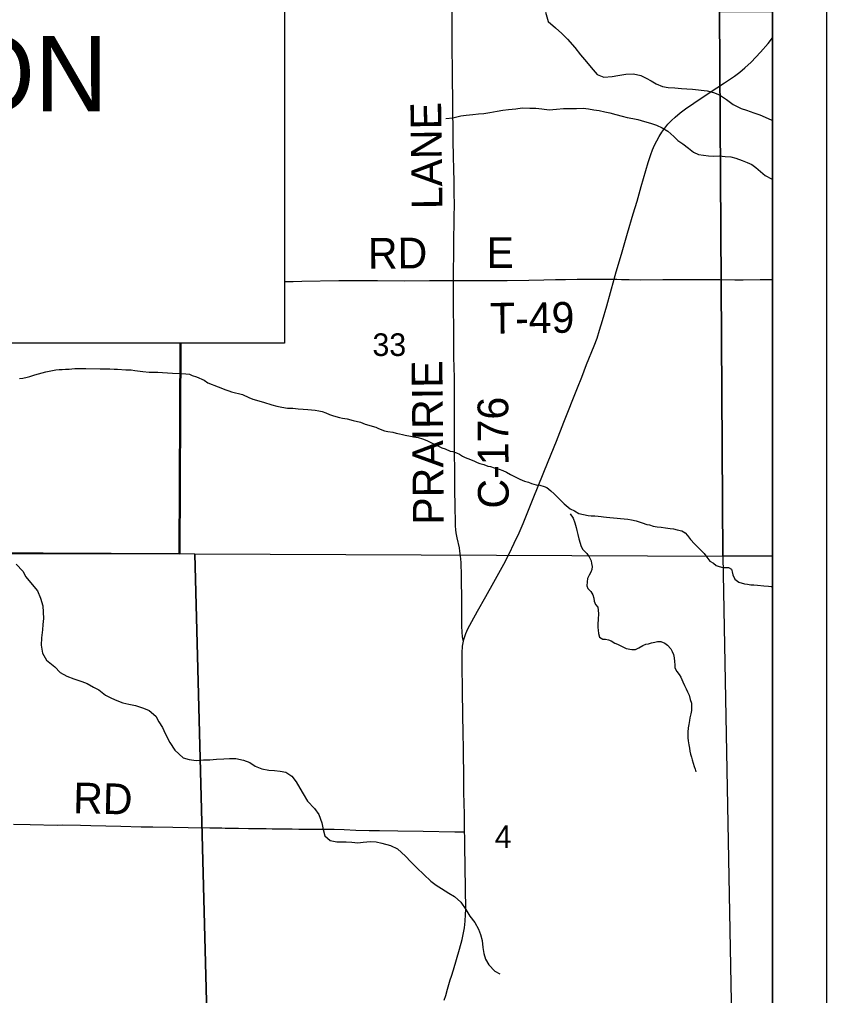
# Model space of a CAD drawing. Extents: x 0 to 34, y 0 to 22.
# Drawn here: x 7.507 to 9, y 15.055 to 16.861 of the extents above; entities that cross this region are included whole.
import ezdxf

# ---------------------------------------------------------------- set-up
doc = ezdxf.new("R2010")
doc.units = 0
for name, color, linetype in [('Default', 7, 'Continuous'), ('GM_X_County_Road', 7, 'Continuous'), ('GM_X_County_Road_Text', 7, 'Continuous'), ('GM_X_Minor_River', 7, 'Continuous'), ('GM_X_Section', 7, 'Continuous'), ('GM_X_Section_Text', 7, 'Continuous'), ('GM_X_State_Route', 7, 'Continuous'), ('GM_X_Township_Road', 7, 'Continuous'), ('GM_X_Township_Road_Text', 7, 'Continuous'), ('SH_Data', 7, 'Continuous'), ('SH_Text', 7, 'Continuous')]:
    doc.layers.add(name, color=color, linetype=linetype)

msp = doc.modelspace()

# ---------------------------------------------------------------- linework, layer by layer
at = {"layer": 'Default'}
for points in [[(8.9, 15.8688), (8.9, 16.8757), (8.802, 16.8756), (8.808, 15.8683)], [(8.9, 14.8441), (8.9, 15.8688), (8.808, 15.8683), (8.8276, 14.8459)]]:
    msp.add_lwpolyline(points, close=True, dxfattribs=at)
at = {"layer": 'GM_X_County_Road'}
for points in [[(8.3101, 16.3785), (8.3101, 16.3991), (8.3103, 16.4239), (8.3109, 16.458), (8.3112, 16.4828), (8.3115, 16.5014), (8.3117, 16.5138), (8.3116, 16.5231), (8.3115, 16.5355), (8.311, 16.5633), (8.3109, 16.5823), (8.3101, 16.61), (8.3096, 16.6348), (8.3093, 16.6501), (8.3091, 16.6686), (8.3089, 16.681), (8.3086, 16.7089), (8.3082, 16.7555), (8.3076, 16.8206), (8.3073, 16.8765)], [(8.3284, 15.7107), (8.3274, 15.7154), (8.3266, 15.7195), (8.326, 15.7272), (8.3257, 15.7394), (8.3251, 15.7821), (8.3245, 15.8316), (8.3239, 15.8564), (8.3231, 15.8686), (8.3219, 15.8777), (8.3209, 15.8838), (8.317, 15.9019), (8.3164, 15.9052), (8.3157, 15.9086), (8.3152, 15.9116), (8.3145, 15.9172), (8.3139, 15.9246), (8.3136, 15.9374), (8.3132, 15.9533), (8.3128, 15.9696), (8.3127, 15.9826), (8.3125, 15.9984), (8.3126, 16.0197), (8.3121, 16.0656), (8.3119, 16.0966), (8.3118, 16.1184), (8.3118, 16.1494), (8.3118, 16.168), (8.3116, 16.1928), (8.3112, 16.2238), (8.3109, 16.2312), (8.3106, 16.2581), (8.3104, 16.2757), (8.3099, 16.3401), (8.3101, 16.3785)]]:
    msp.add_lwpolyline(points, dxfattribs=at)
at = {"layer": 'GM_X_Minor_River'}
for points in [[(8.48, 16.875), (8.4852, 16.858), (8.4985, 16.8463), (8.5107, 16.8354), (8.5206, 16.8248), (8.5343, 16.8097), (8.5449, 16.7961), (8.556, 16.7828), (8.5647, 16.7726), (8.5757, 16.7598), (8.5882, 16.7545), (8.6034, 16.7561), (8.614, 16.7577), (8.6291, 16.7604), (8.6431, 16.7609), (8.6563, 16.7575), (8.6662, 16.7526), (8.6757, 16.7477), (8.6852, 16.7421), (8.6965, 16.7376), (8.7071, 16.7357), (8.7196, 16.735), (8.7317, 16.734), (8.7416, 16.7329), (8.7522, 16.7325), (8.7794, 16.7292), (8.7912, 16.7266), (8.8022, 16.7218), (8.8151, 16.7135), (8.8276, 16.7044), (8.842, 16.6969), (8.8519, 16.6935), (8.8659, 16.6887), (8.8765, 16.6849), (8.8867, 16.6804), (8.8989, 16.6752), (8.9, 16.6744)], [(8.2959, 16.6783), (8.3087, 16.6793), (8.3235, 16.6834), (8.3337, 16.6841), (8.3458, 16.6856), (8.356, 16.6867), (8.3659, 16.6874), (8.3772, 16.6896), (8.3905, 16.6918), (8.4011, 16.6937), (8.4117, 16.6951), (8.4253, 16.6962), (8.437, 16.6981), (8.451, 16.6972), (8.4623, 16.6972), (8.4733, 16.696), (8.4869, 16.6944), (8.5005, 16.6958), (8.5138, 16.6965), (8.5255, 16.6969), (8.5376, 16.6968), (8.5497, 16.6971), (8.5595, 16.6963), (8.5697, 16.6944), (8.5792, 16.6932), (8.5898, 16.6908), (8.5992, 16.6885), (8.6102, 16.6854), (8.6219, 16.6823), (8.6313, 16.68), (8.6415, 16.6781), (8.651, 16.6765), (8.6634, 16.6727), (8.6744, 16.6696), (8.6857, 16.6661), (8.6959, 16.6611), (8.7068, 16.6546), (8.7174, 16.6451), (8.7253, 16.6374), (8.734, 16.6313), (8.7445, 16.6233), (8.754, 16.616), (8.763, 16.6118), (8.7725, 16.6106), (8.7819, 16.6091), (8.7914, 16.6083), (8.8012, 16.609), (8.8126, 16.6082), (8.8228, 16.6074), (8.8322, 16.605), (8.8439, 16.6004), (8.853, 16.5966), (8.8617, 16.5928), (8.8696, 16.5874), (8.8782, 16.5801), (8.8865, 16.5729), (8.8986, 16.5664), (8.9, 16.5657)], [(7.5068, 16.1968), (7.5132, 16.1976), (7.5215, 16.1995), (7.5264, 16.2006), (7.5355, 16.2036), (7.556, 16.2093), (7.562, 16.2108), (7.5681, 16.2119), (7.5745, 16.2131), (7.5806, 16.2134), (7.5863, 16.2138), (7.5923, 16.2146), (7.5987, 16.2145), (7.604, 16.2149), (7.6097, 16.2153), (7.6162, 16.2153), (7.6249, 16.2156), (7.6298, 16.2153), (7.6563, 16.2152), (7.6745, 16.2148), (7.6821, 16.2144), (7.6885, 16.214), (7.7036, 16.2132), (7.7139, 16.2128), (7.7203, 16.2121), (7.7354, 16.2101), (7.7472, 16.209), (7.7548, 16.2086), (7.7627, 16.2086), (7.7718, 16.2082), (7.7809, 16.2074), (7.7904, 16.2066), (7.8048, 16.2062), (7.8146, 16.2058), (7.8214, 16.2051), (7.8263, 16.2028), (7.8343, 16.2001), (7.8487, 16.194), (7.8555, 16.189), (7.8745, 16.1814), (7.8889, 16.1761), (7.8942, 16.1745), (7.8995, 16.1726), (7.9199, 16.1677), (7.9313, 16.1619), (7.9389, 16.1585), (7.9582, 16.1535), (7.9737, 16.1486), (7.9832, 16.1459), (7.9923, 16.144), (8.0029, 16.1424), (8.0127, 16.142), (8.0226, 16.1409), (8.032, 16.1401), (8.0404, 16.1397), (8.0472, 16.1393), (8.054, 16.1386), (8.0608, 16.1374), (8.0669, 16.1359), (8.0737, 16.1336), (8.0805, 16.1305), (8.0881, 16.1279), (8.0991, 16.1248), (8.1044, 16.1237), (8.1131, 16.1225), (8.1241, 16.1194), (8.1377, 16.116), (8.1464, 16.1126), (8.1661, 16.1068), (8.1714, 16.1042), (8.1824, 16.1003), (8.1885, 16.0992), (8.1976, 16.0977), (8.204, 16.0957), (8.2101, 16.0946), (8.2154, 16.0934), (8.2207, 16.0919), (8.2305, 16.0904), (8.2358, 16.0892), (8.2446, 16.0877), (8.2529, 16.0854), (8.2608, 16.082), (8.2658, 16.0797), (8.2715, 16.077), (8.2768, 16.0743), (8.2824, 16.0721)], [(8.2824, 16.0721), (8.2885, 16.069), (8.2946, 16.0667), (8.3037, 16.0625), (8.3086, 16.0618), (8.3154, 16.0595), (8.3211, 16.0568), (8.3264, 16.0534), (8.3317, 16.0507), (8.3416, 16.0473), (8.3488, 16.0442), (8.3537, 16.0415), (8.359, 16.0396), (8.3662, 16.0377), (8.3738, 16.035), (8.3787, 16.0339), (8.3851, 16.0316), (8.3946, 16.0293), (8.4014, 16.0266), (8.4079, 16.0236), (8.4154, 16.0194), (8.4329, 16.011), (8.4416, 16.0072), (8.4488, 16.0049), (8.4541, 16.003), (8.4632, 16.0003), (8.4696, 15.9995), (8.4776, 15.9973), (8.4829, 15.995), (8.4901, 15.9892), (8.4965, 15.9835), (8.5034, 15.9763), (8.5087, 15.971), (8.5147, 15.9653), (8.5261, 15.9561), (8.5337, 15.9519), (8.542, 15.947), (8.5504, 15.9451), (8.5591, 15.9435), (8.5647, 15.9431), (8.5716, 15.9428), (8.5776, 15.942), (8.5829, 15.9416), (8.5878, 15.9412), (8.5932, 15.9404), (8.5992, 15.9397), (8.6125, 15.9385), (8.6189, 15.9377), (8.6325, 15.9366), (8.639, 15.9354), (8.6477, 15.9335), (8.6591, 15.9301), (8.6674, 15.927), (8.6723, 15.9259), (8.6791, 15.924), (8.6867, 15.9228), (8.6939, 15.922), (8.7019, 15.9205), (8.7109, 15.9193), (8.717, 15.9186), (8.7238, 15.917), (8.7325, 15.9151), (8.7386, 15.9113), (8.7428, 15.9064), (8.7485, 15.8988), (8.7561, 15.8911), (8.7633, 15.8835), (8.7682, 15.879), (8.7735, 15.8733), (8.7784, 15.8664), (8.7841, 15.8592), (8.7909, 15.855), (8.7959, 15.8512), (8.8012, 15.8493), (8.808, 15.8474), (8.8129, 15.8473), (8.8186, 15.847), (8.8243, 15.8443), (8.8258, 15.8393), (8.8269, 15.8336), (8.8307, 15.8257), (8.8376, 15.8203), (8.8482, 15.8173), (8.8542, 15.8161), (8.8603, 15.8153), (8.8656, 15.815), (8.8724, 15.8146), (8.8842, 15.8134), (8.8929, 15.813), (8.8978, 15.8122), (8.9, 15.812)], [(8.5257, 15.9466), (8.5314, 15.9386), (8.5345, 15.9299), (8.5371, 15.9215), (8.5383, 15.9158), (8.5402, 15.9086), (8.5421, 15.9002), (8.5463, 15.8862), (8.5493, 15.8805), (8.5565, 15.8732), (8.5611, 15.8668), (8.5645, 15.8595), (8.5656, 15.8546), (8.5668, 15.8489), (8.566, 15.8436), (8.5641, 15.8383), (8.5607, 15.8329), (8.5581, 15.8269), (8.557, 15.8208), (8.5566, 15.8136), (8.5585, 15.8082), (8.5638, 15.8029), (8.5676, 15.7968), (8.5695, 15.7907), (8.5703, 15.7847), (8.5729, 15.7786), (8.5771, 15.7736), (8.5783, 15.7619), (8.5775, 15.7512), (8.5772, 15.7432), (8.5768, 15.736), (8.5775, 15.7311), (8.5783, 15.725), (8.5802, 15.7185), (8.5863, 15.7147), (8.5912, 15.7143), (8.5965, 15.7136), (8.6014, 15.7113), (8.6083, 15.7075), (8.6136, 15.7052), (8.6245, 15.6998), (8.6295, 15.6975), (8.6401, 15.6952), (8.6469, 15.6956), (8.653, 15.6986), (8.6605, 15.7028), (8.6658, 15.7051), (8.6707, 15.7062), (8.6764, 15.7081), (8.6825, 15.7092), (8.6874, 15.7104), (8.6935, 15.7104), (8.7007, 15.7069), (8.7056, 15.7035), (8.712, 15.697), (8.7147, 15.6917), (8.717, 15.686), (8.7181, 15.6799), (8.7189, 15.6731), (8.7193, 15.6674), (8.7197, 15.6617), (8.7234, 15.6548), (8.7276, 15.6491), (8.7303, 15.6442), (8.7341, 15.6354), (8.7371, 15.629), (8.7402, 15.6229), (8.7432, 15.6172), (8.7459, 15.6107), (8.7481, 15.6031), (8.75, 15.5959), (8.7504, 15.5909), (8.7501, 15.5826), (8.7489, 15.5765), (8.7474, 15.5693), (8.7467, 15.5643), (8.7456, 15.5567), (8.744, 15.5503), (8.7437, 15.5427), (8.7433, 15.537), (8.7437, 15.532), (8.7441, 15.5267), (8.7452, 15.5191), (8.7464, 15.513), (8.7471, 15.5073), (8.7487, 15.502), (8.7506, 15.4963), (8.7517, 15.4914), (8.7536, 15.4849), (8.7555, 15.4792), (8.757, 15.4743), (8.7582, 15.4689)], [(7.5011, 15.8533), (7.5133, 15.8405), (7.519, 15.8299), (7.5308, 15.8159), (7.5403, 15.8038), (7.5461, 15.7905), (7.5503, 15.7765), (7.5507, 15.7644), (7.5515, 15.7526), (7.5505, 15.7416), (7.5494, 15.7317), (7.5479, 15.7169), (7.5469, 15.7032), (7.5496, 15.6888), (7.5568, 15.676), (7.5724, 15.6631), (7.5823, 15.6529), (7.5944, 15.6462), (7.6073, 15.6409), (7.6221, 15.6364), (7.6323, 15.6323), (7.6437, 15.6259), (7.6536, 15.6206), (7.6661, 15.6112), (7.6775, 15.6052), (7.6869, 15.6014), (7.6983, 15.5965), (7.7093, 15.5943), (7.7214, 15.5921), (7.7362, 15.5872), (7.7468, 15.5827), (7.759, 15.5722), (7.7647, 15.5619), (7.7719, 15.551), (7.7765, 15.54), (7.7849, 15.5233), (7.7944, 15.5089), (7.81, 15.495), (7.821, 15.4916), (7.8339, 15.4902), (7.8475, 15.491), (7.8592, 15.4914), (7.8713, 15.4926), (7.8853, 15.4931), (7.8955, 15.4939), (7.9073, 15.4939), (7.9213, 15.4906), (7.933, 15.4861), (7.9433, 15.4793), (7.9554, 15.4744), (7.9686, 15.4722), (7.9789, 15.4715)], [(7.9789, 15.4715), (7.9891, 15.4704), (7.9997, 15.4682), (8.0111, 15.461), (8.0187, 15.4504), (8.0259, 15.4391), (8.032, 15.4285), (8.0397, 15.4148), (8.0526, 15.4012), (8.0606, 15.3899), (8.0663, 15.3747), (8.069, 15.3626), (8.0717, 15.3509), (8.082, 15.3418), (8.0941, 15.3396), (8.1115, 15.3393), (8.1217, 15.3386), (8.1331, 15.3379), (8.1429, 15.339), (8.1562, 15.3402), (8.1671, 15.3395), (8.1777, 15.3373), (8.1933, 15.3325), (8.2062, 15.3264), (8.221, 15.3132), (8.2312, 15.3026), (8.2419, 15.2917), (8.2548, 15.2792), (8.2681, 15.2668), (8.278, 15.2596), (8.2878, 15.2532), (8.3015, 15.2445), (8.3121, 15.2385), (8.3235, 15.2276), (8.3327, 15.2143), (8.3403, 15.2018), (8.3494, 15.1901), (8.3563, 15.178), (8.3598, 15.1681), (8.3628, 15.1568), (8.364, 15.1442), (8.366, 15.1329), (8.3694, 15.1223), (8.3752, 15.112), (8.3866, 15.1003), (8.396, 15.0951)]]:
    msp.add_lwpolyline(points, dxfattribs=at)
at = {"layer": 'GM_X_Section'}
for points in [[(7.8054, 16.2626), (7.8036, 15.873), (7.8312, 15.8725), (8.808, 15.8683), (8.802, 16.8756), (7.9972, 16.8792), (7.9972, 16.2626)], [(6.8, 16.2626), (6.7969, 15.8732), (6.8272, 15.8734), (7.8036, 15.873), (7.8054, 16.2626)], [(6.8272, 15.8734), (7.8036, 15.873), (7.8312, 15.8725), (7.8581, 14.855), (6.8411, 14.8726)], [(7.8312, 15.8725), (8.808, 15.8683), (8.8276, 14.8459), (7.8581, 14.855)]]:
    msp.add_lwpolyline(points, close=True, dxfattribs=at)
at = {"layer": 'GM_X_State_Route'}
msp.add_lwpolyline([(7.8042, 16.2626), (7.8024, 15.8725), (6.7968, 15.8774), (5.6416, 15.8841), (5.6436, 15.468), (5.6455, 14.1), (8.9, 14.1), (8.9, 18.8876), (8.7984, 18.8872), (8.8033, 17.8763), (8.296, 17.8766), (7.7904, 17.865), (7.8038, 16.9797), (7.9972, 16.9797), (7.9972, 16.2626)], close=True, dxfattribs=at)
for points in [[(5.6474, 17.3472), (5.6423, 16.0151), (5.6416, 15.8841), (6.7968, 15.8774), (7.8024, 15.8725), (7.8042, 16.2626), (5.7774, 16.2626), (5.7774, 16.9797)], [(8.3265, 15.6987), (8.3268, 15.7018), (8.3278, 15.7078), (8.3284, 15.7107), (8.3291, 15.7138), (8.3309, 15.7196), (8.333, 15.7254), (8.3368, 15.7338), (8.3438, 15.7475), (8.3544, 15.7664), (8.3699, 15.7933), (8.3849, 15.8204), (8.4028, 15.8532), (8.4128, 15.8725), (8.4223, 15.892), (8.4315, 15.9117), (8.4389, 15.9288), (8.4573, 15.9747), (8.4665, 15.9978), (8.4759, 16.0208), (8.4854, 16.0437), (8.5004, 16.0813), (8.5141, 16.116), (8.5391, 16.1796), (8.5472, 16.1997), (8.5563, 16.2228), (8.5701, 16.2574), (8.5755, 16.2719), (8.5802, 16.2867), (8.5856, 16.3046), (8.5934, 16.3315), (8.6072, 16.3808), (8.611, 16.3943), (8.6206, 16.4271), (8.632, 16.4658), (8.6426, 16.5016), (8.6496, 16.5254), (8.6574, 16.5523), (8.6704, 16.5969), (8.6749, 16.6117), (8.6782, 16.6203), (8.6819, 16.6288), (8.686, 16.6371), (8.6905, 16.6452), (8.6954, 16.6531), (8.7008, 16.6606), (8.7067, 16.6678), (8.713, 16.6745), (8.7198, 16.6808), (8.7293, 16.6887), (8.7392, 16.6962), (8.7545, 16.7067), (8.7831, 16.7255), (8.8116, 16.7443), (8.8296, 16.7567), (8.8395, 16.7642), (8.8491, 16.7721), (8.8606, 16.7827), (8.8694, 16.7915), (8.8778, 16.8007), (8.8919, 16.8172), (8.9, 16.8273)], [(8.3301, 15.3832), (8.3301, 15.3883), (8.3298, 15.4131), (8.3294, 15.4287), (8.3294, 15.438), (8.3289, 15.4722), (8.3286, 15.4939), (8.3283, 15.5187), (8.3279, 15.5343), (8.3273, 15.5809), (8.3268, 15.6119), (8.3265, 15.6305), (8.326, 15.6554), (8.3258, 15.6802), (8.326, 15.6926), (8.3265, 15.6987)], [(8.2927, 15.0462), (8.2956, 15.0554), (8.299, 15.0671), (8.304, 15.084), (8.3061, 15.0909), (8.3098, 15.1027), (8.3211, 15.1409), (8.326, 15.1587), (8.3287, 15.1709), (8.3302, 15.1801), (8.3316, 15.1925), (8.3323, 15.2049), (8.3326, 15.2143), (8.3308, 15.3324), (8.3307, 15.3479), (8.3305, 15.3579), (8.3301, 15.3832)]]:
    msp.add_lwpolyline(points, dxfattribs=at)
at = {"layer": 'GM_X_Township_Road'}
for points in [[(7.9972, 16.3767), (8.0029, 16.3767), (8.0136, 16.3767), (8.0293, 16.377), (8.0977, 16.3781), (8.1693, 16.3783), (8.2191, 16.3778), (8.2658, 16.3781), (8.2907, 16.3783), (8.3068, 16.3785), (8.3101, 16.3785)], [(8.3101, 16.3785), (8.344, 16.3786), (8.3875, 16.3784), (8.4092, 16.3785), (8.4495, 16.3792), (8.4773, 16.3798), (8.4988, 16.3803), (8.5172, 16.3805), (8.5389, 16.3806), (8.5762, 16.3808), (8.5936, 16.3811), (8.5989, 16.381), (8.6061, 16.3809), (8.6072, 16.3808)], [(8.6072, 16.3808), (8.6122, 16.3807), (8.6207, 16.3805), (8.635, 16.38), (8.6568, 16.3797), (8.6971, 16.38), (8.725, 16.3802), (8.7561, 16.3801), (8.784, 16.3802), (8.8027, 16.3802), (8.8306, 16.3798), (8.8461, 16.3798), (8.8772, 16.3802), (8.9, 16.3801)], [(7.496, 15.3724), (7.527, 15.3718), (7.5767, 15.3706), (7.586, 15.3707), (7.6201, 15.3701), (7.6388, 15.3697), (7.6947, 15.3684), (7.7319, 15.3675), (7.7537, 15.367), (7.791, 15.3667), (7.819, 15.3661), (7.8594, 15.3655), (7.8749, 15.3652), (7.8811, 15.3652), (7.8874, 15.3651), (7.8998, 15.3648), (7.9122, 15.3646), (7.9307, 15.3645), (7.9506, 15.3641), (7.9637, 15.3639), (7.9744, 15.3637), (7.9804, 15.3635), (7.9933, 15.3634), (8.0025, 15.3634), (8.0114, 15.3633), (8.0238, 15.3631), (8.0331, 15.3629), (8.0456, 15.3631), (8.0634, 15.363), (8.0746, 15.3629), (8.089, 15.3628), (8.1076, 15.3621), (8.1294, 15.3612), (8.1542, 15.3605), (8.1728, 15.3604), (8.207, 15.3598), (8.2536, 15.3591), (8.3123, 15.3581), (8.3247, 15.358), (8.3305, 15.3579)]]:
    msp.add_lwpolyline(points, dxfattribs=at)
at = {"layer": 'SH_Data'}
for p, q in [((9, 21), (9, 14)), ((8.9, 20.9), (8.9, 14.1))]:
    msp.add_line(p, q, dxfattribs=at)
at = {"layer": 'SH_Text'}
msp.add_lwpolyline([(5.7774, 16.9797), (7.9972, 16.9797), (7.9972, 16.2626), (5.7774, 16.2626)], close=True, dxfattribs=at)

# ---------------------------------------------------------------- texts
at = {"layer": 'GM_X_County_Road_Text'}
for s, rotation, p in [('LANE', 90.7332, (8.2896, 16.5105)), ('PRAIRIE', 90.527, (8.2921, 15.9267)), ('C-176', 90.2734, (8.4122, 15.9564))]:
    msp.add_text(s, height=0.05682, rotation=rotation, dxfattribs=at).set_placement(p)
at = {"layer": 'GM_X_Section_Text'}
for s, height, p in [('33', 0.04186, (8.1601, 16.2387)), ('4', 0.0419, (8.3864, 15.3282))]:
    msp.add_text(s, height=height, rotation=0, dxfattribs=at).set_placement(p)
at = {"layer": 'GM_X_Township_Road_Text'}
for s, height, rotation, p in [('RD', 0.05682, 0.4777, (8.1519, 16.4001)), ('E', 0.0568, 0, (8.371, 16.4018)), ('T-49', 0.05682, 0.7052, (8.3777, 16.28)), ('RD', 0.05682, 358.5112, (7.6058, 15.3927))]:
    msp.add_text(s, height=height, rotation=rotation, dxfattribs=at).set_placement(p)
at = {"layer": 'SH_Text'}
msp.add_text('END ACQUISTION', height=0.14, dxfattribs=at).set_placement((6.0584, 16.6912))

doc.saveas('drawing.dxf')
